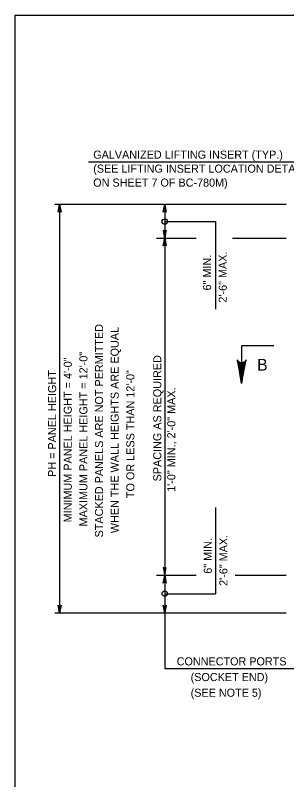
# Model space of a CAD drawing. Extents: x 3385 to 6532, y -616 to 1166.
# Drawn here: x 4642.3 to 4745.6, y 266.5 to 556.7 of the extents above; entities that cross this region are included whole.
import ezdxf

# ---------------------------------------------------------------- set-up
doc = ezdxf.new("R2010")
doc.units = 0
doc.layers.add('1', color=7, linetype='Continuous')
doc.layers.add('2', color=7, linetype='Continuous')

msp = doc.modelspace()

# ---------------------------------------------------------------- linework, layer by layer
at = {"layer": '1'}
for p, q in [((4670.17, 501.11), (4782.49, 501.11)), ((4745.38, 484.9), (4657.34, 484.9)), ((4659.19, 484.9), (4659.19, 329.7)), ((4699.21, 484.9), (4699.21, 308.74)), ((4699.21, 478.39), (4718.55, 478.39)), ((4718.55, 478.39), (4718.55, 445.17)), ((4696.12, 472.1), (4711.15, 472.1)), ((4724.95, 472.1), (4745.38, 472.1)), ((4740.71, 431.16), (4728.44, 431.16)), ((4728.44, 431.16), (4728.44, 416.9)), ((4718.55, 369.88), (4718.55, 337.1)), ((4696.12, 344.1), (4711.15, 344.1)), ((4726.03, 344.1), (4745.38, 344.1)), ((4699.21, 337.1), (4718.55, 337.1)), ((4745.38, 329.7), (4657.34, 329.7)), ((4699.21, 308.74), (4750.96, 308.74))]:
    msp.add_line(p, q, dxfattribs=at)
for points in [[(4659.19, 484.9), (4659.75, 481.92), (4659.59, 482.15), (4659.39, 482.27), (4659.19, 482.3), (4658.99, 482.27), (4658.79, 482.15), (4658.63, 481.92), (4659.19, 484.9), (4658.79, 482.15), (4658.99, 482.27), (4659.19, 484.9), (4659.19, 482.3), (4659.39, 482.27), (4659.19, 484.9), (4659.59, 482.15)], [(4699.21, 484.9), (4699.77, 481.92), (4699.61, 482.15), (4699.41, 482.27), (4699.21, 482.3), (4699.01, 482.27), (4698.81, 482.15), (4698.65, 481.92), (4699.21, 484.9), (4698.81, 482.15), (4699.01, 482.27), (4699.21, 484.9), (4699.21, 482.3), (4699.41, 482.27), (4699.21, 484.9), (4699.61, 482.15)], [(4699.21, 472.1), (4699.77, 475.09), (4699.69, 474.97), (4699.61, 474.86), (4699.51, 474.8), (4699.41, 474.74), (4699.31, 474.72), (4699.21, 474.7), (4699.11, 474.72), (4699.01, 474.74), (4698.91, 474.8), (4698.81, 474.86), (4698.73, 474.97), (4698.65, 475.09), (4699.21, 472.1), (4698.73, 474.97), (4698.81, 474.86), (4699.21, 472.1), (4698.91, 474.8), (4699.01, 474.74), (4699.21, 472.1), (4699.11, 474.72), (4699.21, 474.7), (4699.21, 472.1), (4699.31, 474.72), (4699.41, 474.74), (4699.21, 472.1), (4699.51, 474.8), (4699.61, 474.86), (4699.21, 472.1), (4699.69, 474.97)], [(4699.21, 472.1), (4699.77, 469.12), (4699.69, 469.23), (4699.61, 469.35), (4699.51, 469.41), (4699.41, 469.47), (4699.31, 469.49), (4699.21, 469.5), (4699.11, 469.49), (4699.01, 469.47), (4698.91, 469.41), (4698.81, 469.35), (4698.73, 469.23), (4698.65, 469.12), (4699.21, 472.1), (4698.73, 469.23), (4698.81, 469.35), (4699.21, 472.1), (4698.91, 469.41), (4699.01, 469.47), (4699.21, 472.1), (4699.11, 469.49), (4699.21, 469.5), (4699.21, 472.1), (4699.31, 469.49), (4699.41, 469.47), (4699.21, 472.1), (4699.51, 469.41), (4699.61, 469.35), (4699.21, 472.1), (4699.69, 469.23)], [(4728.44, 416.9), (4730.12, 425.84), (4729.88, 425.5), (4729.64, 425.16), (4729.34, 424.98), (4729.04, 424.8), (4728.74, 424.75), (4728.44, 424.7), (4728.14, 424.75), (4727.84, 424.8), (4727.54, 424.98), (4727.24, 425.16), (4727.01, 425.5), (4726.77, 425.84), (4728.44, 416.9), (4727.01, 425.5), (4727.24, 425.16), (4728.44, 416.9), (4727.54, 424.98), (4727.84, 424.8), (4728.44, 416.9), (4728.14, 424.75), (4728.44, 424.7), (4728.44, 416.9), (4728.74, 424.75), (4729.04, 424.8), (4728.44, 416.9), (4729.34, 424.98), (4729.64, 425.16), (4728.44, 416.9), (4729.88, 425.5)], [(4699.21, 344.1), (4699.77, 347.09), (4699.61, 346.86), (4699.41, 346.74), (4699.21, 346.7), (4699.01, 346.74), (4698.81, 346.86), (4698.65, 347.09), (4699.21, 344.1), (4698.81, 346.86), (4699.01, 346.74), (4699.21, 344.1), (4699.21, 346.7), (4699.41, 346.74), (4699.21, 344.1), (4699.61, 346.86)], [(4699.21, 344.1), (4699.77, 341.12), (4699.61, 341.35), (4699.41, 341.47), (4699.21, 341.5), (4699.01, 341.47), (4698.81, 341.35), (4698.65, 341.12), (4699.21, 344.1), (4698.81, 341.35), (4699.01, 341.47), (4699.21, 344.1), (4699.21, 341.5), (4699.41, 341.47), (4699.21, 344.1), (4699.61, 341.35)], [(4659.19, 329.7), (4658.63, 332.69), (4658.79, 332.46), (4658.99, 332.34), (4659.19, 332.3), (4659.39, 332.34), (4659.59, 332.46), (4659.75, 332.69), (4659.19, 329.7), (4659.59, 332.46), (4659.39, 332.34), (4659.19, 329.7), (4659.19, 332.3), (4658.99, 332.34), (4659.19, 329.7), (4658.79, 332.46)], [(4699.21, 329.7), (4698.65, 332.69), (4698.81, 332.46), (4699.01, 332.34), (4699.21, 332.3), (4699.41, 332.34), (4699.61, 332.46), (4699.77, 332.69), (4699.21, 329.7), (4699.61, 332.46), (4699.41, 332.34), (4699.21, 329.7), (4699.21, 332.3), (4699.01, 332.34), (4699.21, 329.7), (4698.81, 332.46)]]:
    msp.add_lwpolyline(points, dxfattribs=at)
for centre in [(4699.21, 478.39), (4699.21, 337.1)]:
    msp.add_circle(centre, 1.03, dxfattribs=at)
at = {"layer": '2'}
for p, q in [((4642.34, -7.31), (4642.34, 556.69)), ((4642.34, 556.69), (5428.34, 556.69))]:
    msp.add_line(p, q, dxfattribs=at)

# ---------------------------------------------------------------- texts
at = {"layer": '1'}
for s, height, p in [('GALVANIZED LIFTING INSERT (TYP.)', 3.072, (4672, 502.25)), ('(SEE LIFTING INSERT LOCATION DETAIL ', 3.072, (4672, 496.94)), ('ON SHEET 7 OF BC-780M)', 3.072, (4672, 491.63)), ('B', 4.45, (4734.36, 421.81)), ('CONNECTOR PORTS', 3.072, (4703.74, 309.87)), ('(SOCKET END)', 3.072, (4709.05, 303.92)), ('(SEE NOTE 5)', 3.072, (4709.05, 297.97))]:
    msp.add_text(s, height=height, dxfattribs=at).set_placement(p)
for s, p in [('6" MIN.', (4716.83, 452.23)), ('2\'-6" MAX.', (4722.79, 447.62)), ('STACKED PANELS ARE NOT PERMITTED', (4675.74, 358.45)), ('WHEN THE WALL HEIGHTS ARE EQUAL', (4681.69, 360.07)), ('MAXIMUM PANEL HEIGHT = 12\'-0"', (4669.79, 362.64)), ('SPACING AS REQUIRED', (4697.9, 379.73)), ('MINIMUM PANEL HEIGHT = 4\'-0"', (4663.84, 364.17)), ('PH = PANEL HEIGHT', (4657.89, 381.43)), ('TO OR LESS THAN 12\'-0"', (4687.65, 373.39)), ('1\'-0" MIN., 2\'-0" MAX.', (4703.22, 375.77)), ('6" MIN.', (4717.1, 344.68)), ('2\'-6" MAX.', (4723.06, 340.07))]:
    msp.add_text(s, height=3.072, rotation=90, dxfattribs=at).set_placement(p)

doc.saveas('drawing.dxf')
